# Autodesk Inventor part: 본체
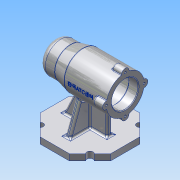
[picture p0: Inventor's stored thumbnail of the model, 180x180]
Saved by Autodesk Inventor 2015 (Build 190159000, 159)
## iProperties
Created: 2019-12
Part Number: 본체
Material: 알루미늄 6061
Document SubType Name: Modeling
Designer: user
Density: 2.7 g/cm^3
Appearance: 알루미늄 - 평지
Mass: 725.94 g
Surface Area: 714.643 cm^2
Volume: 268.867 cm^3
Author: user
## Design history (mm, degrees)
sketch "스케치2"
  geometry: L1 (-80.885, 0)-(78.814, 0) reference; L2 (0, -6)-(0, 36) reference; L3 (-56, 0)-(56, 0); L4 (-56, 0)-(-31, 0); L5 (-31, 0)-(-31, 25); L6 (-31, 25)-(-46, 25); L7 (-56, 15)-(-56, 0); L8 (-31, 0)-(-11, 0); L9 (-11, 0)-(-11, 30); L10 (-31, 25)-(-31, 0); L11 (-11, 0)-(56, 0); L12 (56, 0)-(56, 30); L13 (56, 30)-(-11, 30); L14 (-11, 30)-(-11, 0); L15 (-31, 25)-(-11, 30); A1 r 10 centre (-46, 15) between (-46, 25) and (-56, 15); 2 further points
  constraints: 26 end point, 5 parallel, 4 horizontal, 3 perpendicular, 2 point on circle, 2 point on line, 2 tangent, 1 centre point, 1 collinear, 1 symmetric about line
  dimensions: "d0" = 112 distance of L3.start L3.end; "d1" = 50 diameter of L6 L3; "d2" = 25 distance of L5.end point (-56, 25); "d3" = 45 distance between parallel lines of L7 L9; "d6" = 60 diameter of L9.end L3; "d7" = 112 distance between parallel lines of L7 L12; "d8" = 10 radius of A1
revolve "회전1" sketch "스케치2" stored, may be unused: angle "d9" = 90 deg
sketch "스케치3"
  geometry: L1 (-56, -15)-(-56, 15) reference; L2 (-46, 25)-(-31, 25) reference; L3 (-31, 25)-(-11, 30) reference; L4 (-11, 30)-(56, 30) reference; L5 (56, 30)-(56, -30) reference; L6 (56, -30)-(-11, -30) reference; L7 (-11, -30)-(-31, -25) reference; L8 (-31, -25)-(-46, -25) reference; L9 (-80.885, 0)-(78.814, 0) reference; L10 (-56, 0)-(56, 0); L11 (56, 0)-(41, 0); L12 (41, 0)-(41, 21); L13 (41, 21)-(56, 21); L14 (56, 21)-(56, 0); L15 (41, 0)-(-13, 0); L16 (-13, 0)-(-13, 21); L17 (-10, 24)-(38, 24); L18 (41, 21)-(41, 0); L19 (-13, 0)-(-25, 0); L20 (-25, 0)-(-25, 20.7); L21 (-24.7, 21)-(-13, 21); L22 (-13, 21)-(-13, 0); L23 (-25, 0)-(-43, 0); L24 (-43, 0)-(-43, 17.2); L25 (-42.7, 17.5)-(-25, 17.5); L26 (-25, 17.5)-(-25, 0); L27 (-43, 0)-(-47, 0); L28 (-47, 0)-(-47, 15.7); L29 (-46.7, 16)-(-43, 16); L30 (-43, 16)-(-43, 0); L31 (-47, 0)-(-50, 0); L32 (-50, 0)-(-50, 7.5); L33 (-47, 10.5)-(-47, 10.5); L34 (-47, 10.5)-(-47, 0); A1 r 10 centre (-46, 15) between (-46, 25) and (-56, 15) reference; A2 r 10 centre (-46, -15) between (-56, -15) and (-46, -25) reference; A3 r 0.3 centre (-46.7, 15.7) between (-46.7, 16) and (-47, 15.7); A4 r 0.3 centre (-42.7, 17.2) between (-42.7, 17.5) and (-43, 17.2); A5 r 0.3 centre (-24.7, 20.7) between (-24.7, 21) and (-25, 20.7); A6 r 3 centre (-47, 7.5) between (-47, 10.5) and (-50, 7.5); A7 r 3 centre (-10, 21) between (-10, 24) and (-13, 21); A8 r 3 centre (38, 21) between (41, 21) and (38, 24); 7 further points
  constraints: 50 end point, 12 parallel, 12 point on circle, 12 point on line, 12 tangent, 7 perpendicular, 6 centre point, 6 horizontal, 4 equal radius, 2 midpoint, 1 collinear
  dimensions: "d11" = 42 diameter of L13 L9; "d12" = 48 diameter of L17 L9; "d13" = 15 distance of L12.end L13.end; "d14" = 54 distance of point (-13, 24) point (41, 24); "d15" = 12 distance of point (-25, 21) L21.end; "d16" = 42 diameter of L21 L9; "d17" = 18 distance of point (-43, 17.5) L25.end; "d18" = 35 diameter of L25 L9; "d19" = 32 diameter of L29 L9; "d20" = 21 diameter of L33 L10; "d21" = 3 distance of point (-50, 10.5) L33.end; "d22" = 4 distance of point (-47, 16) L29.end; "d23" = 0.3 radius of A3; "d24" = 3 radius of A6
revolve "회전2" sketch "스케치3" stored, may be unused: angle "d25" = 90 deg
node "작업 평면1"
sketch "스케치4"
  geometry: L1 (0, -42)-(0, 42) reference; L2 (78.4, 0)-(-78.4, 0) reference; L3 (23.196, -56)-(-23.196, -56); L4 (-56, -23.196)-(-56, 23.196); L5 (-23.196, 56)-(23.196, 56); L6 (56, 23.196)-(56, -23.196); L7 (56, 23.196)-(23.196, 56); L8 (-56, 23.196)-(-23.196, 56); L9 (56, -23.196)-(23.196, -56); L10 (-56, -23.196)-(-23.196, -56); C1 r 56 at (0, 0); 1 further point
  constraints: 16 end point, 6 symmetric about line, 5 tangent, 2 parallel, 1 centre point, 1 coincident, 1 horizontal, 1 perpendicular
  dimensions: "d28" = 112 diameter of C1; "d30" = 45 deg angle of L7 L2
extrude "돌출1" join sketch "스케치4" distance "d31" = 10; taper "d32" = 0 deg
sketch "스케치5" dims "d33" = 112
  geometry: L1 (-56, -23.196)-(-23.196, -56) reference; C1 r 5 at (-39.598, -39.598); C2 r 5 at (39.598, -39.598); C3 r 5 at (39.598, 39.598); C4 r 5 at (-39.598, 39.598); 2 further points
  constraints: 4 centre point, 1 coincident, 1 midpoint, 12 other
  dimensions: "d34" = 10 diameter of C1; "d37" = 360 deg dimension on point (0, 0) C1.centre (derived)
extrude "돌출2" cut sketch "스케치5" distance "d39" = 10; taper "d40" = 0 deg
sketch "스케치6"
  geometry: L1 (-56, 23.196)-(-56, -23.196) reference; L2 (56, -23.196)-(56, 23.196) reference; L3 (43.134, 36.062)-(56, 23.196) reference; L4 (56, 23.196)-(56, -23.196) reference; L5 (56, -23.196)-(43.134, -36.062) reference; L6 (36.062, -43.134)-(23.196, -56) reference; L7 (23.196, -56)-(-23.196, -56) reference; L8 (-23.196, -56)-(-36.062, -43.134) reference; L9 (-43.134, -36.062)-(-56, -23.196) reference; L10 (-56, -23.196)-(-56, 23.196) reference; L11 (-56, 23.196)-(-43.134, 36.062) reference; L12 (-36.062, 43.134)-(-23.196, 56) reference; L13 (-23.196, 56)-(23.196, 56) reference; L14 (23.196, 56)-(36.062, 43.134) reference; L15 (78.4, 0)-(-78.4, 0) reference; L16 (0, 78.4)-(0, -78.4) reference; L17 (31, -4)-(-38, -4); L18 (-38, -4)-(-38, 4); L19 (-38, 4)-(31, 4); L20 (31, 4)-(31, -4); A1 r 5 centre (39.598, 39.598) between (36.062, 43.134) and (43.134, 36.062) reference; A2 r 5 centre (39.598, -39.598) between (43.134, -36.062) and (36.062, -43.134) reference; A3 r 5 centre (-39.598, -39.598) between (-36.062, -43.134) and (-43.134, -36.062) reference; A4 r 5 centre (-39.598, 39.598) between (-43.134, 36.062) and (-36.062, 43.134) reference; 1 further point
  constraints: 8 end point, 2 parallel, 1 horizontal, 1 perpendicular, 1 other
  dimensions: "d41" = 8 distance of L19.end L17.start; "d42" = 18 distance between parallel lines of L1 L18; "d43" = 25 distance between parallel lines of L20 L2
extrude "돌출3" join sketch "스케치6" stored distance "d44" = 10; taper "d45" = 0 deg
feature "면 기울기1" dims angle "d46" = 25 deg
sketch "스케치8"
  geometry: L1 (-29.732, -4)-(-70, -4) reference; L2 (-70, -4)-(-70, -56) reference; L3 (-70, -56)-(-80, -56) reference; L4 (-80, -56)-(-80, 56) reference; L5 (-80, 56)-(-70, 56) reference; L6 (-70, 56)-(-70, 4) reference; L7 (-70, 4)-(-29.732, 4) reference; L8 (-70, 36)-(-23.234, 18.979); L9 (-102, 0)-(52, 0) reference; L10 (-70, 36)-(-70, 4); L11 (-70, 4)-(-29.732, 4); C1 r 24 at (0, 0) reference; A1 r 30 centre (0, 0) between (-29.732, -4) and (-29.732, 4) reference; A2 r 30 centre (0, 0) between (-23.234, 18.979) and (-29.732, 4); 1 further point
  constraints: 6 end point, 3 point on circle, 1 centre point, 1 perpendicular, 1 point on line, 1 vertical
  dimensions: "d50" = 110 deg angle of L8 L6; "d51" = 20 distance of L8.start L5.end; "d52" = 30 radius of A2
extrude "돌출4" join sketch "스케치8" stored distance "d53" = 8; taper "d54" = 0 deg
sketch "스케치9"
  geometry: L1 (0, -102)-(0, 52) reference; C1 r 6 at (0, 30); 1 further point
  constraints: 1 centre point, 1 point on line, 1 vertical alignment, 1 other
  dimensions: "d56" = 12 diameter of C1
extrude "돌출5" join sketch "스케치9" distance "d57" = 16; taper "d58" = 0 deg
fillet "모깎기1" dims "d74" = 3
fillet "모깎기2" dims "d75" = 1
fillet "모깎기3" dims "d76" = 3
fillet "모깎기4" dims "d77" = 1
fillet "모깎기5" dims "d78" = 3
fillet "모깎기6" dims "d79" = 3
fillet "모깎기7" dims "d80" = 3
fillet "모깎기8" dims "d81" = 3
chamfer "모따기1" distance "d82" = 1; stored, may be unused: second distance "d83" = 2, angle "d84" = 45 deg
node "작업 평면2"
sketch "스케치10"
  geometry: L1 (33.5, 6.771)-(33.5, 29.226) reference; L2 (-100.9, 0)-(55.9, 0) reference; 2 further points
  constraints: 1 point on line, 1 other
  dimensions: "d85" = 41 distance from line of point (-7.5, 0) L1
feature "엠보싱1" sketch "스케치10" dims "d0" = 112, "d1" = 50, "d2" = 25, "d3" = 45, "d6" = 60, "d7" = 112, "d8" = 10, "d86" = 0.5, "d87" = 0
sketch "스케치11" dims "d88" = 60
  geometry: L1 (0, -133.2)-(0, 29.2) reference; C1 r 22 at (0, -30) reference; 2 further points
  constraints: 1 coincident, 1 point on line, 1 vertical alignment, 2 other
hole "구멍2" sketch "스케치11" at (0, 0) diameter "d89" = 3.242; stored, may be unused: countersink angle "d93" = 90 deg, drill point angle "d95" = 118 deg; dims "d90" = 8, "d91" = 4, "d92" = 2, "d94" = 11
node "솔리드1"
mirror "대칭1"
pattern_circular "원형 패턴1" dims angle "d60" = 360 deg
pattern_circular "원형 패턴3" dims angle "d97" = 360 deg
node "절단 모서리 투영1"
node "절단 모서리 투영2"
node "절단 모서리 투영6"
